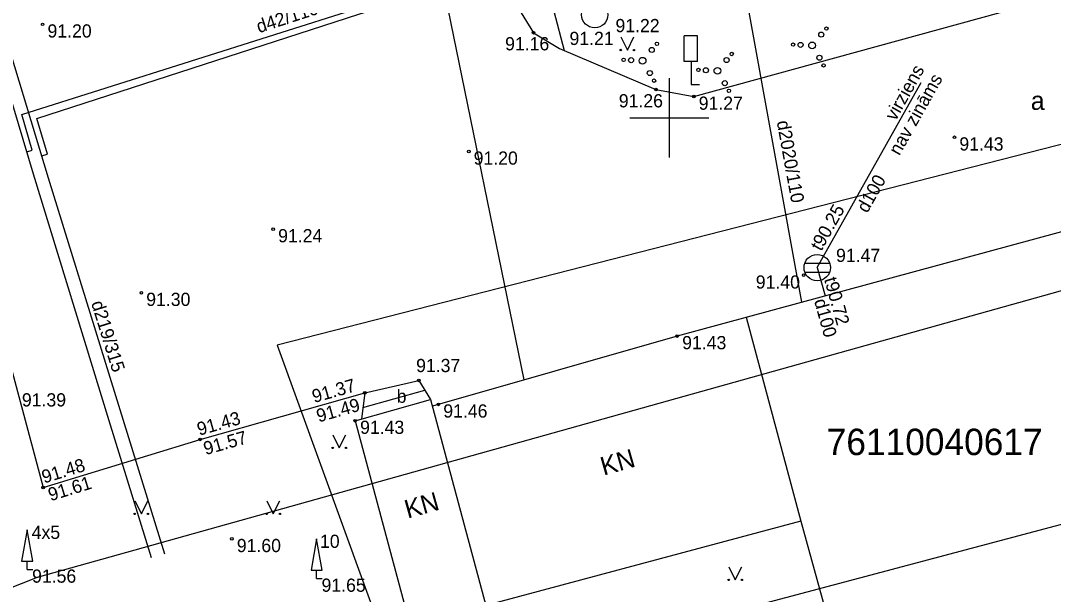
# Model space of a CAD drawing. Extents: x 634272 to 634544, y 247463 to 247653.
# Drawn here: x 634375.43 to 634414.55, y 247531.95 to 247553.68 of the extents above; entities that cross this region are included whole.
import ezdxf

# ---------------------------------------------------------------- set-up
doc = ezdxf.new("R2010")
doc.units = 0
for name, color, linetype in [('BUVE_BDET_####_####_#', 7, 'Continuous'), ('BUVE_BDET_####_TKST_#', 7, 'Continuous'), ('BUVE_EKAS_####_####_#', 7, 'Continuous'), ('BUVE_EKAS_RAKS_TKST_#', 7, 'Continuous'), ('CELI_CAPM_####_####_#', 7, 'Continuous'), ('CELI_CMAL_####_####_#', 7, 'Continuous'), ('CELI_CSEG_####_TKST_#', 7, 'Continuous'), ('CELI_ELEM_####_####_#', 7, 'Continuous'), ('ELEK_VADP_ZSPR_####_#', 7, 'Continuous'), ('GEOD_ELEM_####_####_#', 7, 'Continuous'), ('LKAN_ELEM_####_####_#', 7, 'Continuous'), ('LKAN_ELEM_PAST_TKST_#', 7, 'Continuous'), ('LKAN_VADP_PAST_####_#', 7, 'Continuous'), ('LKAN_VADP_PAST_TKST_#', 7, 'Continuous'), ('RAMI_UZMR_####_####_#', 7, 'Continuous'), ('RELJ_AATZ_####_TKST_#', 7, 'Continuous'), ('RELJ_ELEM_####_####_#', 7, 'Continuous'), ('ROBZ_KADS_####_TKST_#', 7, 'Continuous'), ('ROBZ_UZMR_####_####_#', 7, 'Continuous'), ('SILT_VADP_UDEN_####_#', 7, 'Continuous'), ('SILT_VADP_UDEN_TKST_#', 7, 'Continuous'), ('TERT_DIAM_####_TKST_#', 7, 'Continuous'), ('TERT_ELEM_####_####_#', 7, 'Continuous')]:
    doc.layers.add(name, color=color, linetype=linetype)

msp = doc.modelspace()

# ---------------------------------------------------------------- linework, layer by layer
at = {"layer": 'BUVE_BDET_####_####_#'}
msp.add_line((634388.394, 247539.028), (634390.742, 247539.687), dxfattribs=at)
for points in [[(634388.468, 247539.583), (634390.515, 247540.058), (634390.958, 247539.332)], [(634388.468, 247539.583), (634388.336, 247538.596)]]:
    msp.add_lwpolyline(points, dxfattribs=at)
at = {"layer": 'BUVE_EKAS_####_####_#'}
for q in [(634390.179, 247530.767), (634406.667, 247528.651)]:
    msp.add_line((634404.984, 247534.73), q, dxfattribs=at)
for points in [[(634427.366, 247549.085), (634400.302, 247541.737)], [(634402.918, 247542.447), (634404.984, 247534.73)], [(634400.302, 247541.737), (634391.024, 247539.084)], [(634388.101, 247538.53), (634390.958, 247539.332)], [(634390.958, 247539.332), (634393.045, 247531.534)], [(634388.101, 247538.53), (634390.179, 247530.767)]]:
    msp.add_lwpolyline(points, dxfattribs=at)
at = {"layer": 'CELI_CAPM_####_####_#'}
for points in [[(634386.18, 247584.245), (634386.517, 247583.098), (634389.042, 247573.196), (634391.897, 247562.219), (634393.7, 247555.164), (634394.221, 247554.237), (634394.857, 247553.225), (634395.836, 247552.623), (634399.496, 247551.073), (634400.928, 247550.806), (634417.097, 247555.253), (634426.457, 247557.809), (634427.052, 247555.379), (634437.491, 247558.047), (634462.278, 247564.311)], [(634368.714, 247564.266), (634372.374, 247550.548), (634376.283, 247536.001), (634382.231, 247537.822), (634388.468, 247539.583)]]:
    msp.add_lwpolyline(points, dxfattribs=at)
at = {"layer": 'CELI_CMAL_####_####_#'}
msp.add_lwpolyline([(634397.071, 247591.031), (634391.102, 247589.18), (634389.241, 247588.463), (634387.877, 247587.668), (634387.466, 247585.812), (634389.236, 247579.186), (634390.091, 247575.648), (634392.378, 247566.891), (634395.219, 247556.093), (634395.631, 247554.043), (634396.02, 247552.545)], dxfattribs=at)
at = {"layer": 'CELI_ELEM_####_####_#'}
for p, q in [((634401.069, 247553.107), (634400.569, 247553.107)), ((634400.569, 247552.138), (634400.569, 247553.107)), ((634401.069, 247552.138), (634401.069, 247553.107)), ((634401.069, 247552.138), (634400.569, 247552.138)), ((634400.823, 247552.138), (634400.823, 247551.26)), ((634400.823, 247551.26), (634401.138, 247551.26))]:
    msp.add_line(p, q, dxfattribs=at)
at = {"layer": 'ELEK_VADP_ZSPR_####_#'}
msp.add_lwpolyline([(634391.846, 247587.255), (634391.785, 247587.453), (634390.617, 247588.23), (634384.398, 247586.285), (634384.012, 247585.121), (634391.398, 247555.188), (634394.49, 247540.075)], dxfattribs=at)
at = {"layer": 'GEOD_ELEM_####_####_#'}
for p, q in [((634400, 247551.5), (634400, 247550)), ((634398.5, 247550), (634400, 247550)), ((634400, 247550), (634400, 247548.5)), ((634400, 247550), (634401.5, 247550))]:
    msp.add_line(p, q, dxfattribs=at)
at = {"layer": 'LKAN_ELEM_####_####_#'}
for p, q in [((634405.137, 247544.501), (634406.073, 247544.501)), ((634405.137, 247544.151), (634406.073, 247544.151))]:
    msp.add_line(p, q, dxfattribs=at)
for centre in [(634397.175, 247553.907), (634405.605, 247544.326)]:
    msp.add_circle(centre, 0.5, dxfattribs=at)
at = {"layer": 'LKAN_VADP_PAST_####_#'}
for points in [[(634405.605, 247544.326), (634409.546, 247551.342)], [(634405.605, 247544.326), (634405.903, 247543.258)]]:
    msp.add_lwpolyline(points, dxfattribs=at)
at = {"layer": 'RAMI_UZMR_####_####_#'}
msp.add_lwpolyline([(634466.614, 247558.36), (634469.076, 247546.545), (634471.781, 247533.982), (634471.429, 247521.859), (634457.577, 247518.735), (634456.257, 247517.942), (634433.742, 247506.986), (634428.158, 247503.509), (634420.457, 247500.517), (634407.71, 247496.821), (634397.043, 247493.687), (634395.968, 247498.053), (634390.559, 247517.942), (634387.41, 247527.318), (634427.834, 247538.059), (634425.364, 247546.393), (634376.048, 247532.596), (634371.988, 247530.992)], dxfattribs=at)
at = {"layer": 'RELJ_ELEM_####_####_#'}
for centre in [(634376.26, 247553.542), (634394.857, 247553.225), (634399.496, 247551.073), (634400.928, 247550.806), (634410.803, 247549.263), (634392.403, 247548.727), (634384.996, 247545.787), (634405.09, 247544.042), (634380, 247543.376), (634400.302, 247541.737), (634390.515, 247540.058), (634388.468, 247539.583), (634391.253, 247539.149), (634388.101, 247538.53), (634382.231, 247537.822), (634376.283, 247536.001), (634383.431, 247534.052)]:
    msp.add_circle(centre, 0.05, dxfattribs=at)
at = {"layer": 'ROBZ_UZMR_####_####_#'}
for points in [[(634428.904, 247552.595), (634385.149, 247541.391)], [(634385.149, 247541.391), (634393.309, 247518.933)]]:
    msp.add_lwpolyline(points, dxfattribs=at)
at = {"layer": 'SILT_VADP_UDEN_####_#'}
msp.add_line((634402.715, 247555.675), (634405.012, 247543.016), dxfattribs=at)
for points in [[(634380.38, 247533.332), (634378.785, 247538.524), (634375.914, 247547.864), (634373.98, 247554.308), (634372.046, 247560.751), (634368.919, 247572.314), (634365.801, 247584.167), (634363.457, 247593.328)], [(634363.886, 247593.437), (634366.36, 247583.831), (634369.421, 247572.245), (634372.593, 247560.517), (634376.47, 247547.723), (634378.808, 247540.177), (634380.88, 247533.487)], [(634375.66, 247548.71), (634375.865, 247548.771), (634375.478, 247550.132), (634388.249, 247554.171), (634398.315, 247557.303)], [(634376.217, 247548.559), (634376.441, 247548.623), (634376.038, 247549.97), (634388.236, 247553.927), (634398.375, 247557.07)]]:
    msp.add_lwpolyline(points, dxfattribs=at)
at = {"layer": 'TERT_ELEM_####_####_#'}
for p, q in [((634398.162, 247553.068), (634398.412, 247552.568)), ((634398.412, 247552.568), (634398.662, 247553.068)), ((634387.25, 247538), (634387.5, 247537.5)), ((634387.5, 247537.5), (634387.75, 247538)), ((634379.75, 247535.5), (634380, 247535)), ((634380, 247535), (634380.25, 247535.5)), ((634384.75, 247535.5), (634385, 247535)), ((634385, 247535), (634385.25, 247535.5)), ((634375.675, 247532.894), (634375.675, 247533.214)), ((634375.675, 247532.894), (634375.885, 247532.894)), ((634402.25, 247533), (634402.5, 247532.5)), ((634402.5, 247532.5), (634402.75, 247533)), ((634386.641, 247532.55), (634386.641, 247532.87)), ((634386.641, 247532.55), (634386.851, 247532.55))]:
    msp.add_line(p, q, dxfattribs=at)
for points in [[(634375.465, 247533.214), (634375.885, 247533.214), (634375.675, 247534.394)], [(634386.431, 247532.87), (634386.851, 247532.87), (634386.641, 247534.05)]]:
    msp.add_lwpolyline(points, close=True, dxfattribs=at)
for centre, radius in [((634405.757, 247553.151), 0.096), ((634405.953, 247553.382), 0.064), ((634399.532, 247552.803), 0.064), ((634404.975, 247552.764), 0.096), ((634405.409, 247552.743), 0.128), ((634398.161, 247552.568), 0.028), ((634398.661, 247552.568), 0.0263), ((634399.336, 247552.572), 0.096), ((634402.367, 247552.419), 0.064), ((634404.691, 247552.777), 0.064), ((634398.27, 247552.198), 0.064), ((634398.554, 247552.185), 0.096), ((634398.988, 247552.164), 0.128), ((634402.171, 247552.188), 0.096), ((634405.685, 247552.276), 0.096), ((634399.264, 247551.697), 0.096), ((634401.105, 247551.814), 0.064), ((634401.389, 247551.801), 0.096), ((634401.823, 247551.78), 0.128), ((634405.843, 247551.987), 0.064), ((634399.422, 247551.408), 0.064), ((634402.099, 247551.313), 0.096), ((634402.257, 247551.024), 0.064), ((634387.25, 247537.5), 0.028), ((634387.75, 247537.5), 0.0263), ((634379.75, 247535), 0.028), ((634380.25, 247535), 0.0263), ((634384.75, 247535), 0.028), ((634385.25, 247535), 0.0263), ((634402.25, 247532.5), 0.028), ((634402.75, 247532.5), 0.0263)]:
    msp.add_circle(centre, radius, dxfattribs=at)

# ---------------------------------------------------------------- texts
at = {"layer": 'BUVE_BDET_####_TKST_#'}
msp.add_text('b', height=0.5, dxfattribs=at).set_placement((634389.673, 247539.207))
at = {"layer": 'BUVE_EKAS_RAKS_TKST_#'}
for rotation, p in [(15.9604, (634397.511, 247536.446)), (15.6802, (634390.087, 247534.819))]:
    msp.add_text('KN', height=0.7, rotation=rotation, dxfattribs=at).set_placement(p)
at = {"layer": 'CELI_CSEG_####_TKST_#'}
msp.add_text('a', height=0.7, dxfattribs=at).set_placement((634413.695, 247550.301))
at = {"layer": 'LKAN_ELEM_PAST_TKST_#'}
for s, p in [(' 91.21', (634396.034, 247552.759)), (' 91.47', (634406.131, 247544.542))]:
    msp.add_text(s, height=0.5, dxfattribs=at).set_placement(p)
at = {"layer": 'LKAN_VADP_PAST_TKST_#'}
for s, rotation, p in [('virziens', 60.6772, (634408.571, 247549.854)), ('nav zināms', 60.6772, (634408.717, 247548.543)), ('d100', 60.6772, (634407.499, 247546.366)), ('t90.25', 60.6772, (634405.753, 247544.921)), ('t90.72', 285.5626, (634405.859, 247543.891)), ('d100', 285.5626, (634405.48, 247543.074))]:
    msp.add_text(s, height=0.5, rotation=rotation, dxfattribs=at).set_placement(p)
at = {"layer": 'RELJ_AATZ_####_TKST_#'}
for s, p in [(' 91.22', (634397.775, 247553.245)), (' 91.20', (634376.26, 247553.042)), (' 91.16', (634393.594, 247552.556)), (' 91.26', (634397.901, 247550.397)), (' 91.27', (634400.928, 247550.306)), (' 91.43', (634410.803, 247548.763)), (' 91.20', (634392.403, 247548.227)), (' 91.24', (634384.996, 247545.287)), (' 91.40', (634403.09, 247543.533)), (' 91.30', (634380, 247542.876)), (' 91.43', (634400.302, 247541.237)), (' 91.37', (634390.223, 247540.37)), (' 91.39', (634375.29, 247539.069)), (' 91.46', (634391.253, 247538.649)), (' 91.43', (634388.101, 247538.03)), (' 91.60', (634383.431, 247533.552)), (' 91.56', (634375.675, 247532.394)), (' 91.56', (634375.675, 247532.394)), (' 91.65', (634386.641, 247532.05)), (' 91.65', (634386.641, 247532.05))]:
    msp.add_text(s, height=0.5, dxfattribs=at).set_placement(p)
for s, rotation, p in [(' 91.37', 15.7669, (634386.368, 247539.147)), (' 91.49', 15.7669, (634386.536, 247538.411)), (' 91.43', 15.7669, (634382.012, 247537.907)), (' 91.57', 15.7669, (634382.257, 247537.174)), (' 91.48', 17.0221, (634376.138, 247536.094)), (' 91.61', 17.0221, (634376.383, 247535.423))]:
    msp.add_text(s, height=0.5, rotation=rotation, dxfattribs=at).set_placement(p)
at = {"layer": 'ROBZ_KADS_####_TKST_#'}
msp.add_text('76110040617', height=1, dxfattribs=at).set_placement((634405.962, 247537.227))
at = {"layer": 'SILT_VADP_UDEN_TKST_#'}
for s, rotation, p in [('d42/110', 17.9729, (634384.455, 247553.204)), ('d2020/110', 280.284, (634404.067, 247549.856)), ('d219/315', 287.2136, (634378.094, 247542.989))]:
    msp.add_text(s, height=0.5, rotation=rotation, dxfattribs=at).set_placement(p)
at = {"layer": 'TERT_DIAM_####_TKST_#'}
for s, p in [('4x5', (634375.846, 247534.053)), ('10', (634386.768, 247533.713))]:
    msp.add_text(s, height=0.5, dxfattribs=at).set_placement(p)

doc.saveas('drawing.dxf')
